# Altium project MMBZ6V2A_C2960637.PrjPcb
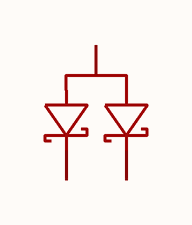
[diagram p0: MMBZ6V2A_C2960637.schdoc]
1 sheet, 1 parts. Net scope: global (net labels, ports and power ports of the same name join across sheets).

## Sheet MMBZ6V2A_C2960637.schdoc
size 127 x 101 mm

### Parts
U?  mmbz6v2a_c2960637  [SOT-23-3_L2.9-W1.3-P1.90-LS2.4-BR]  (value not drawn)

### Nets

Not connected (* = marked no-connect by the designer): U? 1 2 3

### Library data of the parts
U? = mmbz6v2a_c2960637: 极性:单向;反向截止电压(Vrwm):3V;钳位电压:8.7V;峰值脉冲电流(Ipp):2.76A;峰值脉冲功率(Ppp):24W;击穿电压(VBR):5.89V;; Manufacturer: JSMSEMI(杰盛微); AddInBom: yes; ModelId: c62791f0466c4ae2a892c056b845b0ca; ModelName: SOT-23-3P_L2.9-W1.3-H1.0-LS2.4-P0.95; ModelTransform: 98.425,114.173,0,180,0,0,0.0005,-0.0005,0; Polarity: 单向; Reverse Stand-Off Voltage (Vrwm): 3V; Clamping Voltage: 8.7V; Peak Pulse Current (Ipp): 2.76A; Peak Pulse Power Dissipation (Ppp): 24W; Voltage - Breakdown: 5.89V; Reverse Leakage Current (Ir): 500nA; Number of Channels: 双路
